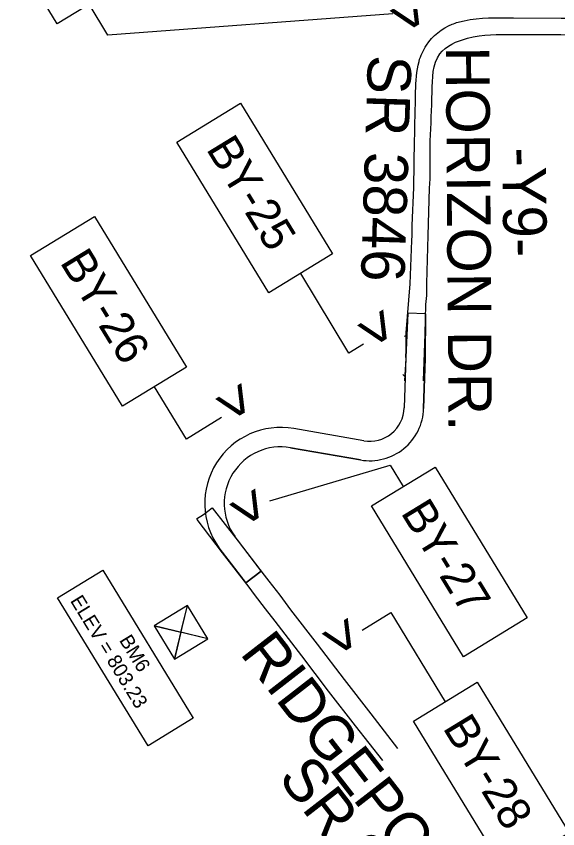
# Model space of a CAD drawing. Extents: x 1771071 to 1790027, y 804210 to 823391.
# Drawn here: x 1779527 to 1780140, y 814798 to 815717 of the extents above; entities that cross this region are included whole.
import ezdxf

# ---------------------------------------------------------------- set-up
doc = ezdxf.new("R2010")
doc.units = 0
for name, color, linetype in [('Default', 7, 'Continuous'), ('Exist Roads EOP', 7, 'Continuous'), ('Old_Level_57', 7, 'Continuous'), ('Prop Conc 5in Monolithic Surface Mount Island', 7, 'Continuous'), ('Proposed Right of Way Monument PSD Text', 7, 'Continuous'), ('Scratch_Level_1', 7, 'Continuous'), ('Scratch_Level_7', 7, 'Continuous'), ('Scratch_Level_8', 7, 'Continuous')]:
    doc.layers.add(name, color=color, linetype=linetype)

msp = doc.modelspace()

# ---------------------------------------------------------------- linework, layer by layer
at = {"layer": 'Default'}
for points in [[(1779541.65, 815923.05), (1779645.77, 815752.64), (1779573.65, 815708.57), (1779469.53, 815878.98)], [(1779781.08, 815618.68), (1779885.2, 815448.27), (1779813.08, 815404.21), (1779708.96, 815574.62)], [(1779615.71, 815490.57), (1779719.83, 815320.16), (1779647.71, 815276.09), (1779543.59, 815446.5)], [(1780001.17, 815207.39), (1780105.29, 815036.98), (1780033.17, 814992.92), (1779929.05, 815163.33)], [(1779625.36, 815090.82), (1779727.62, 814923.46), (1779676.42, 814892.18), (1779574.16, 815059.54)], [(1780048.64, 814964.02), (1780152.76, 814793.61), (1780080.64, 814749.55), (1779976.52, 814919.95)]]:
    msp.add_lwpolyline(points, close=True, dxfattribs=at)
for points in [[(1779953.11, 815719.67), (1779631, 815695.76), (1779609.71, 815730.61)], [(1779920.12, 815346.43), (1779903.36, 815336), (1779849.14, 815426.24)], [(1779759.67, 815263.22), (1779720.02, 815238.81), (1779683.78, 815298.13)], [(1779813.98, 815169.24), (1779950.31, 815209.59), (1779965.11, 815185.36)], [(1779918.74, 815023.05), (1779950.96, 815042.85), (1780012.58, 814941.99)]]:
    msp.add_lwpolyline(points, dxfattribs=at)
at = {"layer": 'Exist Roads EOP'}
for points in [[(1780089.57, 815715.2), (1780143.52, 815714.96), (1780196.9, 815714.8), (1780248.96, 815713.54), (1780288.49, 815715.72)], [(1780089.54, 815696.41), (1780143.4, 815696.53), (1780197.37, 815696.05), (1780249.15, 815694.02)], [(1779966.65, 815304.99), (1779968.17, 815329.92), (1779968.35, 815344.09), (1779968.46, 815359.25), (1779972.69, 815414.58), (1779974.84, 815463.63), (1779975.07, 815469.09), (1779975.05, 815480.52), (1779977.03, 815523.3), (1779977.86, 815576.91)], [(1779988.01, 815304.88), (1779989.82, 815358.07), (1779990.6, 815390.99), (1779991.73, 815401.17), (1779991.56, 815415.09), (1779993.34, 815469.21), (1779994.82, 815522.8), (1779995.44, 815533.31), (1779995.59, 815542.38), (1779995.48, 815576.37)], [(1779731.19, 815148.68), (1779739.28, 815153.7), (1779748.94, 815161.21), (1779778.29, 815123.43), (1779807.88, 815085.04), (1779813.18, 815078.49), (1779825.32, 815062.63), (1779837.62, 815046.03), (1779867.6, 815007.05), (1779898.36, 814967.08), (1779928.28, 814928.26), (1779958.46, 814889.16)], [(1779941.78, 814875.39), (1779911.17, 814914.78), (1779880.68, 814954.04), (1779850.22, 814993.99), (1779820.11, 815033.08), (1779809.08, 815047.12), (1779796.95, 815063.34), (1779790.82, 815071.49), (1779760.73, 815110.28), (1779731.84, 815147.91)]]:
    msp.add_lwpolyline(points, dxfattribs=at)
for points in [[(1779977.86, 815576.91), (1779979.05, 815631.87), (1779982.84, 815666.12), (1779991.21, 815684.28), (1780020.35, 815708.07), (1780033.94, 815712.11), (1780089.57, 815715.2)], [(1779995.48, 815576.37), (1779997.66, 815631.34), (1780006.37, 815674.5), (1780037.67, 815692.31), (1780089.54, 815696.41)]]:
    msp.add_spline(points, degree=3, dxfattribs=at)
at = {"layer": 'Old_Level_57'}
for p, q in [((1779706.32, 814990.13), (1779721, 815050.93)), ((1779744.06, 815013.19), (1779683.26, 815027.87))]:
    msp.add_line(p, q, dxfattribs=at)
msp.add_lwpolyline([(1779721, 815050.93), (1779683.26, 815027.87), (1779706.32, 814990.13), (1779744.06, 815013.19)], close=True, dxfattribs=at)
for points in [[(1779713.66, 815020.53), (1779721, 815050.93), (1779683.26, 815027.87), (1779713.66, 815020.53)], [(1779713.66, 815020.53), (1779706.32, 814990.13), (1779744.06, 815013.19), (1779713.66, 815020.53)]]:
    msp.add_lwpolyline(points, dxfattribs=at)
at = {"layer": 'Prop Conc 5in Monolithic Surface Mount Island'}
for p, q in [((1779967.94, 815331.28), (1779970.14, 815381.24)), ((1779990.35, 815380.59), (1779970.14, 815381.24)), ((1779990.35, 815380.59), (1779989.93, 815330.58)), ((1779967.94, 815331.28), (1779966.11, 815274.26)), ((1779989.93, 815330.58), (1779988.1, 815273.55)), ((1779920.43, 815237.09), (1779841.37, 815250.88)), ((1779916.65, 815215.42), (1779837.59, 815229.2)), ((1779804.4, 815089.55), (1779787.19, 815076.32))]:
    msp.add_line(p, q, dxfattribs=at)
for centre, radius, start, end in [((1779927.13, 815275.51), 61, 260.10938, 358.16184), ((1779927.13, 815275.51), 39, 260.10938, 358.16184), ((1779826.59, 815166.16), 86, 80.10938, 215.4204), ((1779826.59, 815166.16), 64, 80.10938, 215.4204)]:
    msp.add_arc(centre, radius, start, end, dxfattribs=at)
for points in [[(1779774.44, 815129.06), (1779774.77, 815128.59), (1779775.11, 815128.12), (1779775.45, 815127.66), (1779775.8, 815127.2), (1779776.2, 815126.67), (1779776.6, 815126.13), (1779777.01, 815125.6), (1779777.42, 815125.06), (1779777.83, 815124.52), (1779778.24, 815123.98), (1779778.65, 815123.44), (1779779.06, 815122.91), (1779779.47, 815122.37), (1779779.87, 815121.83), (1779780.28, 815121.29), (1779780.69, 815120.75), (1779781.1, 815120.22), (1779781.51, 815119.68), (1779781.92, 815119.14), (1779782.33, 815118.6), (1779782.74, 815118.06), (1779783.14, 815117.53), (1779783.55, 815116.99), (1779783.96, 815116.45), (1779784.37, 815115.91), (1779784.78, 815115.37), (1779785.19, 815114.84), (1779785.6, 815114.3), (1779786.01, 815113.76), (1779786.41, 815113.22), (1779786.82, 815112.68), (1779787.23, 815112.14), (1779787.64, 815111.61), (1779788.05, 815111.07), (1779788.46, 815110.53), (1779788.87, 815109.99), (1779789.28, 815109.45), (1779789.68, 815108.92), (1779790.09, 815108.38), (1779790.5, 815107.84), (1779790.91, 815107.3), (1779791.32, 815106.76), (1779791.73, 815106.23), (1779792.14, 815105.69), (1779792.55, 815105.15), (1779792.95, 815104.61), (1779793.36, 815104.07), (1779793.77, 815103.54), (1779794.18, 815103), (1779794.59, 815102.46), (1779795, 815101.92), (1779795.41, 815101.38), (1779795.82, 815100.85), (1779796.23, 815100.31), (1779796.63, 815099.77), (1779797.04, 815099.23), (1779797.45, 815098.69), (1779797.86, 815098.16), (1779798.27, 815097.62), (1779798.68, 815097.08), (1779799.09, 815096.54), (1779799.5, 815096), (1779799.9, 815095.47), (1779800.31, 815094.93), (1779800.72, 815094.39), (1779801.13, 815093.85), (1779801.54, 815093.31), (1779801.95, 815092.78), (1779802.36, 815092.24), (1779802.77, 815091.7), (1779803.17, 815091.16), (1779803.58, 815090.62), (1779804.4, 815089.55)], [(1779756.51, 815116.31), (1779756.96, 815115.68), (1779757.42, 815115.06), (1779757.88, 815114.44), (1779758.35, 815113.82), (1779758.77, 815113.27), (1779759.18, 815112.74), (1779759.6, 815112.2), (1779760.01, 815111.67), (1779760.42, 815111.13), (1779760.83, 815110.59), (1779761.24, 815110.06), (1779761.66, 815109.52), (1779762.07, 815108.99), (1779762.48, 815108.45), (1779762.89, 815107.92), (1779763.3, 815107.38), (1779763.71, 815106.85), (1779764.13, 815106.31), (1779764.54, 815105.77), (1779764.95, 815105.24), (1779765.36, 815104.7), (1779765.77, 815104.17), (1779766.19, 815103.63), (1779766.6, 815103.1), (1779767.01, 815102.56), (1779767.42, 815102.02), (1779767.83, 815101.49), (1779768.25, 815100.95), (1779768.66, 815100.42), (1779769.07, 815099.88), (1779769.48, 815099.35), (1779769.89, 815098.81), (1779770.31, 815098.28), (1779770.72, 815097.74), (1779771.13, 815097.2), (1779771.54, 815096.67), (1779771.95, 815096.13), (1779772.36, 815095.6), (1779772.78, 815095.06), (1779773.19, 815094.53), (1779773.6, 815093.99), (1779774.01, 815093.46), (1779774.42, 815092.92), (1779774.84, 815092.38), (1779775.25, 815091.85), (1779775.66, 815091.31), (1779776.07, 815090.78), (1779776.48, 815090.24), (1779776.9, 815089.71), (1779777.31, 815089.17), (1779777.72, 815088.63), (1779778.13, 815088.1), (1779778.54, 815087.56), (1779778.96, 815087.03), (1779779.37, 815086.49), (1779779.78, 815085.96), (1779780.19, 815085.42), (1779780.6, 815084.89), (1779781.02, 815084.35), (1779781.43, 815083.81), (1779781.84, 815083.28), (1779782.25, 815082.74), (1779782.66, 815082.21), (1779783.07, 815081.67), (1779783.49, 815081.14), (1779783.9, 815080.6), (1779784.31, 815080.07), (1779784.72, 815079.53), (1779785.13, 815078.99), (1779785.55, 815078.46), (1779785.96, 815077.92), (1779786.37, 815077.39), (1779787.19, 815076.32)]]:
    msp.add_spline(points, degree=3, dxfattribs=at)
at = {"layer": 'Scratch_Level_1'}
for p, q in [((1779966.57, 815355.37), (1779968.36, 815356.18)), ((1779964.69, 815312.15), (1779966.95, 815309.56))]:
    msp.add_line(p, q, dxfattribs=at)
at = {"layer": 'Scratch_Level_8'}
for p, q in [((1779970.14, 815381.24), (1779967.94, 815331.28)), ((1779990.35, 815380.59), (1779970.14, 815381.24)), ((1779989.93, 815330.58), (1779990.35, 815380.59)), ((1779967.94, 815331.28), (1779966.11, 815274.26)), ((1779988.1, 815273.55), (1779989.93, 815330.58)), ((1779920.43, 815237.09), (1779841.37, 815250.88)), ((1779837.59, 815229.2), (1779916.65, 815215.42)), ((1779787.19, 815076.32), (1779804.4, 815089.55))]:
    msp.add_line(p, q, dxfattribs=at)
for centre, radius, start, end in [((1779927.13, 815275.51), 61, 260.10938, 358.16184), ((1779927.13, 815275.51), 39, 260.10938, 358.16184), ((1779826.59, 815166.16), 86, 80.10938, 215.4204), ((1779826.59, 815166.16), 64, 80.10938, 215.4204)]:
    msp.add_arc(centre, radius, start, end, dxfattribs=at)
for points in [[(1779784.4, 815115.87), (1779784.39, 815115.89), (1779784.38, 815115.9), (1779784.37, 815115.91), (1779784.23, 815116.09), (1779784.1, 815116.27), (1779783.96, 815116.45), (1779783.83, 815116.63), (1779783.69, 815116.81), (1779783.55, 815116.99), (1779783.42, 815117.17), (1779783.28, 815117.35), (1779783.14, 815117.53), (1779783.01, 815117.7), (1779782.87, 815117.88), (1779782.74, 815118.06), (1779782.6, 815118.24), (1779782.46, 815118.42), (1779782.33, 815118.6), (1779782.19, 815118.78), (1779782.05, 815118.96), (1779781.92, 815119.14), (1779781.78, 815119.32), (1779781.65, 815119.5), (1779781.51, 815119.68), (1779781.37, 815119.86), (1779781.24, 815120.04), (1779781.1, 815120.22), (1779780.96, 815120.39), (1779780.83, 815120.57), (1779780.69, 815120.75), (1779780.56, 815120.93), (1779780.42, 815121.11), (1779780.28, 815121.29), (1779780.15, 815121.47), (1779780.01, 815121.65), (1779779.87, 815121.83), (1779779.74, 815122.01), (1779779.6, 815122.19), (1779779.47, 815122.37), (1779779.33, 815122.55), (1779779.19, 815122.73), (1779779.06, 815122.91), (1779778.92, 815123.08), (1779778.78, 815123.26), (1779778.65, 815123.44), (1779778.51, 815123.62), (1779778.38, 815123.8), (1779778.24, 815123.98), (1779778.1, 815124.16), (1779777.97, 815124.34), (1779777.83, 815124.52), (1779777.69, 815124.7), (1779777.56, 815124.88), (1779777.42, 815125.06), (1779777.29, 815125.24), (1779777.15, 815125.42), (1779777.01, 815125.6), (1779776.88, 815125.77), (1779776.74, 815125.95), (1779776.6, 815126.13), (1779776.47, 815126.31), (1779776.33, 815126.49), (1779776.2, 815126.67), (1779776.06, 815126.85), (1779775.93, 815127.02), (1779775.8, 815127.2), (1779775.68, 815127.35), (1779775.56, 815127.51), (1779775.45, 815127.66), (1779775.34, 815127.81), (1779775.22, 815127.97), (1779775.11, 815128.12), (1779775, 815128.28), (1779774.88, 815128.44), (1779774.77, 815128.59), (1779774.66, 815128.75), (1779774.55, 815128.91), (1779774.44, 815129.06)], [(1779756.51, 815116.31), (1779756.66, 815116.1), (1779756.81, 815115.89), (1779756.96, 815115.68), (1779757.11, 815115.47), (1779757.27, 815115.27), (1779757.42, 815115.06), (1779757.57, 815114.85), (1779757.73, 815114.64), (1779757.88, 815114.44), (1779758.04, 815114.23), (1779758.19, 815114.02), (1779758.35, 815113.82), (1779758.49, 815113.64), (1779758.63, 815113.45), (1779758.77, 815113.27), (1779758.91, 815113.09), (1779759.05, 815112.92), (1779759.18, 815112.74), (1779759.32, 815112.56), (1779759.46, 815112.38), (1779759.6, 815112.2), (1779759.73, 815112.02), (1779759.87, 815111.84), (1779760.01, 815111.67), (1779760.14, 815111.49), (1779760.28, 815111.31), (1779760.42, 815111.13), (1779760.56, 815110.95), (1779760.69, 815110.77), (1779760.83, 815110.59), (1779760.97, 815110.42), (1779761.11, 815110.24), (1779761.24, 815110.06), (1779761.38, 815109.88), (1779761.52, 815109.7), (1779761.66, 815109.52), (1779761.79, 815109.34), (1779761.93, 815109.17), (1779762.07, 815108.99), (1779762.2, 815108.81), (1779762.34, 815108.63), (1779762.48, 815108.45), (1779762.62, 815108.27), (1779762.75, 815108.09), (1779762.89, 815107.92), (1779763.03, 815107.74), (1779763.17, 815107.56), (1779763.3, 815107.38), (1779763.44, 815107.2), (1779763.58, 815107.02), (1779763.71, 815106.85), (1779763.85, 815106.67), (1779763.99, 815106.49), (1779764.13, 815106.31), (1779764.26, 815106.13), (1779764.4, 815105.95), (1779764.54, 815105.77), (1779764.68, 815105.6), (1779764.81, 815105.42), (1779764.95, 815105.24), (1779765.09, 815105.06), (1779765.23, 815104.88), (1779765.36, 815104.7), (1779765.5, 815104.52), (1779765.64, 815104.35), (1779765.77, 815104.17), (1779765.91, 815103.99), (1779766.05, 815103.81), (1779766.19, 815103.63), (1779766.32, 815103.45), (1779766.46, 815103.27), (1779766.6, 815103.1), (1779766.63, 815103.05), (1779766.67, 815103), (1779766.71, 815102.96)], [(1779794.4, 815102.71), (1779794.33, 815102.81), (1779794.25, 815102.9), (1779794.18, 815103), (1779794.04, 815103.18), (1779793.91, 815103.36), (1779793.77, 815103.54), (1779793.64, 815103.72), (1779793.5, 815103.9), (1779793.36, 815104.07), (1779793.23, 815104.25), (1779793.09, 815104.43), (1779792.95, 815104.61), (1779792.82, 815104.79), (1779792.68, 815104.97), (1779792.55, 815105.15), (1779792.41, 815105.33), (1779792.27, 815105.51), (1779792.14, 815105.69), (1779792, 815105.87), (1779791.86, 815106.05), (1779791.73, 815106.23), (1779791.59, 815106.41), (1779791.46, 815106.59), (1779791.32, 815106.76), (1779791.18, 815106.94), (1779791.05, 815107.12), (1779790.91, 815107.3), (1779790.77, 815107.48), (1779790.64, 815107.66), (1779790.5, 815107.84), (1779790.37, 815108.02), (1779790.23, 815108.2), (1779790.09, 815108.38), (1779789.96, 815108.56), (1779789.82, 815108.74), (1779789.68, 815108.92), (1779789.55, 815109.1), (1779789.41, 815109.28), (1779789.28, 815109.45), (1779789.14, 815109.63), (1779789, 815109.81), (1779788.87, 815109.99), (1779788.73, 815110.17), (1779788.59, 815110.35), (1779788.46, 815110.53), (1779788.32, 815110.71), (1779788.19, 815110.89), (1779788.05, 815111.07), (1779787.91, 815111.25), (1779787.78, 815111.43), (1779787.64, 815111.61), (1779787.5, 815111.79), (1779787.37, 815111.97), (1779787.23, 815112.14), (1779787.1, 815112.32), (1779786.96, 815112.5), (1779786.82, 815112.68), (1779786.69, 815112.86), (1779786.55, 815113.04), (1779786.41, 815113.22), (1779786.28, 815113.4), (1779786.14, 815113.58), (1779786.01, 815113.76), (1779785.87, 815113.94), (1779785.73, 815114.12), (1779785.6, 815114.3), (1779785.46, 815114.48), (1779785.32, 815114.66), (1779785.19, 815114.84), (1779785.05, 815115.01), (1779784.92, 815115.19), (1779784.78, 815115.37), (1779784.65, 815115.54), (1779784.53, 815115.71), (1779784.4, 815115.87)], [(1779766.71, 815102.96), (1779766.81, 815102.82), (1779766.91, 815102.69), (1779767.01, 815102.56), (1779767.15, 815102.38), (1779767.28, 815102.2), (1779767.42, 815102.02), (1779767.56, 815101.85), (1779767.7, 815101.67), (1779767.83, 815101.49), (1779767.97, 815101.31), (1779768.11, 815101.13), (1779768.25, 815100.95), (1779768.38, 815100.77), (1779768.52, 815100.6), (1779768.66, 815100.42), (1779768.79, 815100.24), (1779768.93, 815100.06), (1779769.07, 815099.88), (1779769.21, 815099.7), (1779769.34, 815099.53), (1779769.48, 815099.35), (1779769.62, 815099.17), (1779769.76, 815098.99), (1779769.89, 815098.81), (1779770.03, 815098.63), (1779770.17, 815098.45), (1779770.31, 815098.28), (1779770.44, 815098.1), (1779770.58, 815097.92), (1779770.72, 815097.74), (1779770.85, 815097.56), (1779770.99, 815097.38), (1779771.13, 815097.2), (1779771.27, 815097.03), (1779771.4, 815096.85), (1779771.54, 815096.67), (1779771.68, 815096.49), (1779771.82, 815096.31), (1779771.95, 815096.13), (1779772.09, 815095.95), (1779772.23, 815095.78), (1779772.36, 815095.6), (1779772.5, 815095.42), (1779772.64, 815095.24), (1779772.78, 815095.06), (1779772.91, 815094.88), (1779773.05, 815094.7), (1779773.19, 815094.53), (1779773.33, 815094.35), (1779773.46, 815094.17), (1779773.6, 815093.99), (1779773.74, 815093.81), (1779773.88, 815093.63), (1779774.01, 815093.46), (1779774.15, 815093.28), (1779774.29, 815093.1), (1779774.42, 815092.92), (1779774.56, 815092.74), (1779774.7, 815092.56), (1779774.84, 815092.38), (1779774.97, 815092.21), (1779775.11, 815092.03), (1779775.25, 815091.85), (1779775.39, 815091.67), (1779775.52, 815091.49), (1779775.66, 815091.31), (1779775.8, 815091.13), (1779775.93, 815090.96), (1779776.07, 815090.78), (1779776.21, 815090.6), (1779776.35, 815090.42), (1779776.48, 815090.24), (1779776.62, 815090.06), (1779776.76, 815089.88), (1779776.9, 815089.71), (1779776.91, 815089.68), (1779776.93, 815089.66), (1779776.95, 815089.64)], [(1779804.4, 815089.55), (1779804.13, 815089.91), (1779803.86, 815090.27), (1779803.58, 815090.62), (1779803.45, 815090.8), (1779803.31, 815090.98), (1779803.17, 815091.16), (1779803.04, 815091.34), (1779802.9, 815091.52), (1779802.77, 815091.7), (1779802.63, 815091.88), (1779802.49, 815092.06), (1779802.36, 815092.24), (1779802.22, 815092.42), (1779802.08, 815092.6), (1779801.95, 815092.78), (1779801.81, 815092.96), (1779801.68, 815093.13), (1779801.54, 815093.31), (1779801.4, 815093.49), (1779801.27, 815093.67), (1779801.13, 815093.85), (1779800.99, 815094.03), (1779800.86, 815094.21), (1779800.72, 815094.39), (1779800.59, 815094.57), (1779800.45, 815094.75), (1779800.31, 815094.93), (1779800.18, 815095.11), (1779800.04, 815095.29), (1779799.9, 815095.47), (1779799.77, 815095.65), (1779799.63, 815095.83), (1779799.5, 815096), (1779799.36, 815096.18), (1779799.22, 815096.36), (1779799.09, 815096.54), (1779798.95, 815096.72), (1779798.81, 815096.9), (1779798.68, 815097.08), (1779798.54, 815097.26), (1779798.41, 815097.44), (1779798.27, 815097.62), (1779798.13, 815097.8), (1779798, 815097.98), (1779797.86, 815098.16), (1779797.72, 815098.34), (1779797.59, 815098.52), (1779797.45, 815098.69), (1779797.32, 815098.87), (1779797.18, 815099.05), (1779797.04, 815099.23), (1779796.91, 815099.41), (1779796.77, 815099.59), (1779796.63, 815099.77), (1779796.5, 815099.95), (1779796.36, 815100.13), (1779796.23, 815100.31), (1779796.09, 815100.49), (1779795.95, 815100.67), (1779795.82, 815100.85), (1779795.68, 815101.03), (1779795.54, 815101.21), (1779795.41, 815101.38), (1779795.27, 815101.56), (1779795.14, 815101.74), (1779795, 815101.92), (1779794.86, 815102.1), (1779794.73, 815102.28), (1779794.59, 815102.46), (1779794.53, 815102.54), (1779794.46, 815102.63), (1779794.4, 815102.71)], [(1779776.95, 815089.64), (1779777.07, 815089.48), (1779777.19, 815089.33), (1779777.31, 815089.17), (1779777.45, 815088.99), (1779777.58, 815088.81), (1779777.72, 815088.63), (1779777.86, 815088.46), (1779777.99, 815088.28), (1779778.13, 815088.1), (1779778.27, 815087.92), (1779778.41, 815087.74), (1779778.54, 815087.56), (1779778.68, 815087.38), (1779778.82, 815087.21), (1779778.96, 815087.03), (1779779.09, 815086.85), (1779779.23, 815086.67), (1779779.37, 815086.49), (1779779.5, 815086.31), (1779779.64, 815086.14), (1779779.78, 815085.96), (1779779.92, 815085.78), (1779780.05, 815085.6), (1779780.19, 815085.42), (1779780.33, 815085.24), (1779780.47, 815085.06), (1779780.6, 815084.89), (1779780.74, 815084.71), (1779780.88, 815084.53), (1779781.02, 815084.35), (1779781.15, 815084.17), (1779781.29, 815083.99), (1779781.43, 815083.81), (1779781.56, 815083.64), (1779781.7, 815083.46), (1779781.84, 815083.28), (1779781.98, 815083.1), (1779782.11, 815082.92), (1779782.25, 815082.74), (1779782.39, 815082.56), (1779782.53, 815082.39), (1779782.66, 815082.21), (1779782.8, 815082.03), (1779782.94, 815081.85), (1779783.07, 815081.67), (1779783.21, 815081.49), (1779783.35, 815081.31), (1779783.49, 815081.14), (1779783.62, 815080.96), (1779783.76, 815080.78), (1779783.9, 815080.6), (1779784.04, 815080.42), (1779784.17, 815080.24), (1779784.31, 815080.07), (1779784.45, 815079.89), (1779784.58, 815079.71), (1779784.72, 815079.53), (1779784.86, 815079.35), (1779785, 815079.17), (1779785.13, 815078.99), (1779785.27, 815078.82), (1779785.41, 815078.64), (1779785.55, 815078.46), (1779785.68, 815078.28), (1779785.82, 815078.1), (1779785.96, 815077.92), (1779786.1, 815077.74), (1779786.23, 815077.57), (1779786.37, 815077.39), (1779786.64, 815077.03), (1779786.92, 815076.67), (1779787.19, 815076.32)]]:
    msp.add_open_spline(points, degree=3, dxfattribs=at)

# ---------------------------------------------------------------- texts
at = {"layer": 'Old_Level_57'}
for p in [(1779943.52, 815723.2), (1779906.8, 815367.51), (1779746.37, 815284.26), (1779761.99, 815164.98), (1779866.75, 815018.79)]:
    msp.add_text('>', height=46.95, rotation=301.43915, dxfattribs=at).set_placement(p)
at = {"layer": 'Proposed Right of Way Monument PSD Text'}
for s, height, p in [('BY-25', 37.325, (1779741.48, 815567.15)), ('BY-26', 37.325, (1779576.12, 815439.04)), ('BY-27', 37.325, (1779961.58, 815155.86)), ('ELEV = 803.23', 16, (1779587.91, 815056.22)), ('BM6', 16, (1779643.33, 815011.54)), ('BY-28', 37.325, (1780009.05, 814912.49))]:
    msp.add_text(s, height=height, rotation=301.42495, dxfattribs=at).set_placement(p)
at = {"layer": 'Scratch_Level_7'}
for s, height, rotation, p in [('HORIZON DR.', 49.2075, 270.39749, (1780013.23, 815682.76)), ('SR 3846', 49.208, 268.18932, (1779925.22, 815673.7)), ('-Y9-', 49.208, 270.78385, (1780076.78, 815568.55)), ('RIDGEPOINT DR.', 49.2075, 307.80364, (1779779.38, 814996.63)), ('BEGIN BRIDGE', 100, 301.40172, (1779271.49, 814860.5)), ('SR 3652', 49.208, 307.80364, (1779822.48, 814855.65))]:
    msp.add_text(s, height=height, rotation=rotation, dxfattribs=at).set_placement(p)

doc.saveas('drawing.dxf')
